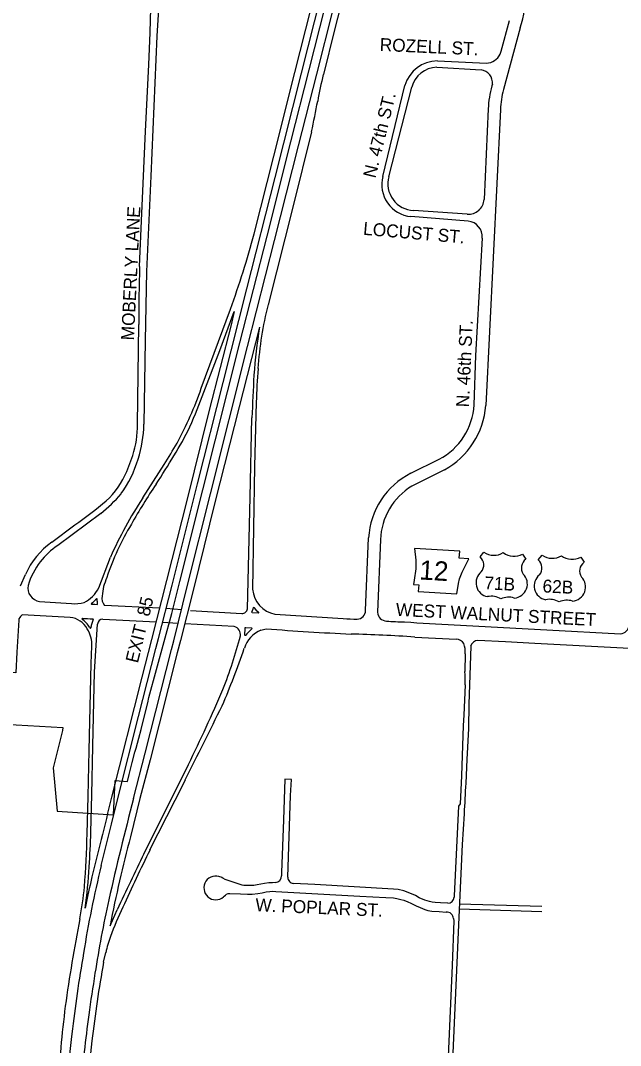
# Model space of a CAD drawing. Extents: x 0 to 712119, y 0 to 761125.
# Drawn here: x 668635 to 670960, y 734082 to 738055 of the extents above; entities that cross this region are included whole.
import ezdxf

# ---------------------------------------------------------------- set-up
doc = ezdxf.new("R2010")
doc.units = 0
for name, color, linetype in [('city boundary', 7, 'Continuous'), ('Exit #s', 7, 'Continuous'), ('HWY signs', 7, 'Continuous'), ('PAVED ROADS', 7, 'Continuous'), ('street names', 7, 'Continuous')]:
    doc.layers.add(name, color=color, linetype=linetype)

msp = doc.modelspace()

# ---------------------------------------------------------------- linework, layer by layer
at = {"layer": 'city boundary'}
msp.add_lwpolyline([(668436.5, 735335.1), (668799.7, 735315.2), (668798.5, 735303.7), (668762.3, 735158.2), (668776.8, 734990.1), (668995.9, 734976.3), (669002.2, 735108.9), (669049.3, 735105.9), (669056, 735132.9), (669067.6, 735179.7), (669077.6, 735219.5), (669083.7, 735234.7), (669093.4, 735273.9), (669102.4, 735306.9), (669116.4, 735365.2), (669128.1, 735411.1), (669133, 735431.7), (669221, 735756.7), (669252.5, 735881.3), (669341.5, 736235.9), (669485.3, 736806.3), (669591, 737219.4), (669683, 737585.7), (669753.1, 737863.7), (669877.4, 738354.3)], dxfattribs=at)
at = {"layer": 'HWY signs'}
msp.add_lwpolyline([(670325.4, 735832.6), (670331.9, 735873), (670336.6, 735890.7), (670346.8, 735917.4), (670357.6, 735939.8), (670372.3, 735968.9), (670335.4, 735971.1), (670337, 735998.5), (670161.6, 736009.1), (670167, 735963.5), (670166.5, 735930.4), (670160.9, 735886.1), (670158, 735868.6), (670178.2, 735867.4), (670176.6, 735841.6)], close=True, dxfattribs=at)
for points in [[(670415.9, 735976.2), (670430.9, 735994.7)], [(670505.9, 735992.7), (670505.9, 735992.7)], [(670580.6, 735986.9), (670593.6, 735967)], [(670641.4, 735964.5), (670656.5, 735982.9)], [(670731.4, 735980.9), (670731.4, 735980.9)], [(670806.1, 735975.1), (670819.2, 735955.2)]]:
    msp.add_lwpolyline(points, dxfattribs=at)
for centre, radius, start, end in [((670388.7, 735944.9), 41.5, 320.1078, 49.1208), ((670469.9, 736050.8), 68.4, 235.2382, 301.7199), ((670547.7, 736046.8), 68.4, 232.3011, 298.7827), ((670617.4, 735933), 41.5, 124.9002, 213.9131), ((670614.2, 735933.1), 41.5, 320.1078, 49.1208), ((670695.4, 736039.1), 68.4, 235.2382, 301.7199), ((670773.2, 736035), 68.4, 232.3011, 298.7827), ((670454.6, 735875.8), 54.5, 128.6765, 259.9158), ((670842.9, 735921.2), 41.5, 124.9002, 213.9131), ((670544.7, 735871.1), 54.5, 274.1051, 45.3444), ((670680.1, 735864), 54.5, 128.6765, 259.9158), ((670770.2, 735859.3), 54.5, 274.1051, 45.3444), ((670459.4, 735750), 73.6, 59.7374, 101.2498), ((670526.8, 735746.4), 73.6, 72.7711, 114.2835), ((670684.9, 735738.2), 73.6, 59.7374, 101.2498), ((670752.3, 735734.7), 73.6, 72.7711, 114.2835)]:
    msp.add_arc(centre, radius, start, end, dxfattribs=at)
at = {"layer": 'PAVED ROADS'}
for points in [[(668947.9, 734779.4), (668988.3, 734940.4), (669013, 735044.3), (669091.8, 735357.5), (669159.4, 735621.1), (669170.4, 735660.5), (669222.6, 735866.3), (669320.6, 736259.4), (669420.1, 736652.6), (669512.8, 737015.7), (669621.8, 737446.7), (669724.1, 737851.2), (669851.1, 738352.5)], [(669073.1, 735040.2), (669117.9, 735215.3), (669220.1, 735617.2), (669228.7, 735650.4), (669282.8, 735866.3), (669371.2, 736220.6), (669515.1, 736792.2), (669619.8, 737203.2), (669712.7, 737570.2), (669783.1, 737847.8), (669910.5, 738349.5)], [(669096.8, 737101.7), (669104.2, 737279.4), (669120.1, 737626.9), (669132, 737883.6), (669137.1, 738009.3), (669147.2, 738340.5)], [(669540.8, 737228.7), (669616.5, 737529.2), (669698.4, 737853.5), (669825, 738353.5)], [(669935.5, 738347.4), (669852.2, 738018.6), (669808.6, 737846.6)], [(669180.8, 738339.2), (669173.7, 738163.6), (669163.5, 737994.6), (669140.2, 737451.6), (669123.6, 737082.4), (669118.6, 736815.3), (669113.3, 736490.2)], [(670493.5, 737925.5), (670497.5, 737936), (670530, 738055.5)], [(670571.5, 738027), (670506.5, 737787.5)], [(670248, 737874), (670420, 737864.5)], [(670250.5, 737898.5), (670440.5, 737890)], [(670039, 737451), (670125, 737804)], [(670062.5, 737450), (670151.2, 737796.5)], [(670464, 737808), (670462, 737802)], [(670447.4, 737713.1), (670431.5, 737361.5)], [(670494.5, 737710.5), (670437.9, 736563.2)], [(670447.4, 737713.1), (670447.4, 737713.1)], [(669763, 737624), (669691.4, 737336.9), (669594.7, 736953.9)], [(670366.4, 737304.5), (670158.5, 737319.5)], [(670369.5, 737278), (670147.5, 737295.5)], [(670392.6, 736565.6), (670399.6, 736756.6), (670424.7, 737211.7)], [(669345.4, 736614.6), (669407, 736776.4), (669463.4, 736927.7), (669450.9, 736876.1), (669366.6, 736545.1), (669279.5, 736195.1), (669143.4, 735656.2), (669105.8, 735510.6), (668988.1, 735044.4)], [(669335.6, 736630.1), (669402.4, 736810.7), (669448.9, 736936.2)], [(669088.8, 736489.8), (669093.1, 736877)], [(669561.1, 736866.5), (669482.1, 736558.5), (669388, 736186.9), (669305, 735851.3), (669254.7, 735651.5), (669242.4, 735604.6), (669137, 735189.4), (669098.2, 735040), (669061.2, 734891.4)], [(669548.6, 736575.8), (669541.4, 736326.2), (669534.7, 735850.7)], [(669514.6, 735775.3), (669525.2, 736207.1), (669532, 736514.7)], [(669047.1, 736307.5), (669070.7, 736369.6)], [(670148, 736300.3), (670257.3, 736354.5)], [(669109, 736204.7), (669192.1, 736334.7)], [(670278, 736313.4), (670151.3, 736250.7)], [(668946, 736144.7), (668779.3, 736020.5)], [(668756.3, 736032.8), (668845.5, 736099.9)], [(669972.2, 735768.4), (669983.8, 736050.1)], [(670029.6, 736043), (670019.1, 735761.4)], [(668938.4, 735855.9), (668983.5, 735975.2)], [(668635.2, 735863.5), (668654.2, 735907.7)], [(668708.7, 735803.1), (668832.8, 735795.6)], [(668827.3, 735741.4), (668642.1, 735751.1), (668635.4, 735745.3), (668632.2, 735741), (668629.2, 735735.5), (668628.7, 735730.6), (668620.8, 735606.4), (668617.6, 735527.4), (668590.6, 735527.9), (668595.6, 735628.9), (668599.1, 735724.9), (668599, 735728.8), (668598.9, 735732.7), (668598.6, 735736.4), (668597.5, 735742.1), (668595.8, 735746.6), (668593.2, 735751), (668588.7, 735752.7), (668579.2, 735754.4), (668532.3, 735757.2), (668296.5, 735776.9)], [(669173.7, 735777.5), (668960.8, 735788.3)], [(669258.4, 735771.4), (669199.9, 735775.6)], [(669294.4, 735768), (669492.3, 735757.1)], [(668873.6, 735734.5), (668873.6, 735734.5)], [(669245.2, 735717.9), (669186.4, 735721.5)], [(669620.7, 735753.8), (669885.5, 735737.1)], [(668903.2, 735703.3), (668905.3, 735700.3)], [(668907.8, 734909.1), (668911.3, 735053.3), (668915.1, 735242.6), (668922.2, 735530.4), (668933.3, 735715.8)], [(669463.1, 735705.8), (669271.6, 735716.8)], [(669566.6, 735692.5), (669587.2, 735697.5)], [(670315.7, 735712.3), (670674.2, 735694.1), (670960, 735678)], [(670163.6, 735665.6), (670242.8, 735660.8), (670323.9, 735657.2)], [(671664, 735592), (671344.7, 735603.9), (670995.3, 735620.5), (670627.9, 735640.5), (670515, 735647.1), (670407.6, 735652.5)], [(668893.7, 734902.3), (668897.6, 735048), (668901, 735226), (668908.9, 735563.3), (668912, 735629.7)], [(670358.1, 735600.7), (670357.1, 735531.6)], [(670379.5, 735629.9), (670372.7, 735404.8), (670371.4, 735311.1), (670364.2, 735191.4), (670360.5, 735098.8)], [(670357.8, 735479.8), (670352.7, 735362.7), (670350.7, 735322.6), (670344.1, 735127.5), (670338.2, 735019.4), (670331.9, 735009.9), (670316, 734663), (670316, 734657.5)], [(669112.9, 734825.2), (669215.8, 735030.9), (669285.8, 735172)], [(669136.9, 734841), (669234.5, 735033.8), (669273.9, 735112.2)], [(669671.4, 734734.3), (669682, 735051), (669685, 735113.5), (669659, 735114.5), (669654.5, 734957.5), (669647, 734753), (669646.9, 734740.5)], [(670354.2, 734980.4), (670346.7, 734861.8), (670333, 734579.2), (670322.8, 734344.7), (670306.5, 733965.5), (670286.7, 733516.2), (670268, 733065.2)], [(669623.2, 734713.5), (669612, 734713.3), (669597.5, 734712.7), (669580.8, 734710.8), (669566.1, 734708.2), (669551.6, 734704.6), (669539.3, 734702.6), (669525.3, 734702), (669513, 734701.9), (669500.1, 734703), (669493.8, 734704.3), (669428.4, 734726.1), (669418.6, 734731), (669412.1, 734734.6)], [(670290.5, 734634), (670262, 734635.5), (670242.5, 734636.5), (670230, 734637.5), (670220.5, 734640), (670202.5, 734646), (670180.5, 734655), (670165.5, 734663.5), (670144, 734673), (670120, 734681.5), (670098, 734686.5), (670081, 734688.5), (669776, 734706), (669692.9, 734710.4)], [(669421.9, 734658), (669425, 734661.5), (669429, 734665.5), (669434, 734669), (669439.5, 734671), (669446, 734671.5), (669487.5, 734669.5), (669514.5, 734668.5), (669533, 734669), (669554.5, 734671), (669572, 734674), (669586.5, 734677.5), (669601, 734679.5), (669611.5, 734680), (669625, 734679.5), (669950, 734661.5), (670050.5, 734656), (670080.5, 734654.5), (670094, 734652), (670109.5, 734648.5), (670121, 734645), (670136, 734639), (670148, 734634), (670168.5, 734623), (670184, 734617), (670202.5, 734610), (670213.5, 734606), (670228.5, 734603), (670258, 734601), (670285, 734599.5)], [(668982.1, 734545.8), (669010.1, 734608.7)], [(670334.9, 734611.9), (670654.9, 734602.2)], [(670335.5, 734631.9), (670655.5, 734622.2)], [(670312.5, 734574), (670314.5, 734565.5), (670308.4, 734391.9), (670292.4, 734039.4), (670278, 733725.7), (670264.5, 733399.3), (670250.1, 733065.8), (670248.3, 733062.6)], [(668957.4, 734405.5), (668965.4, 734442.1)]]:
    msp.add_lwpolyline(points, dxfattribs=at)
for points in [[(668930.9, 735813.6), (668926.3, 735809.5), (668919.4, 735803.4), (668913.6, 735798.5), (668908.5, 735794.5), (668909.8, 735793.5), (668923.7, 735792.5), (668933.4, 735792.3), (668933.4, 735792.3), (668934, 735793.6), (668933.7, 735797.6), (668933.5, 735800), (668933.1, 735802.5), (668932.9, 735805.3), (668932.6, 735808.6), (668932.3, 735813.1)], [(669539.4, 735780.5), (669547.4, 735771.6), (669557.3, 735761.3), (669557.1, 735759.8), (669556.2, 735758.4), (669533, 735759.2), (669532.3, 735760), (669532.2, 735762), (669534.6, 735768.4), (669537, 735775.3), (669538.2, 735780.1), (669538.7, 735780.9)], [(669504.8, 735673.3), (669505.4, 735699.6), (669506.2, 735702.2), (669508.2, 735703), (669530.3, 735701.2), (669532.3, 735698.9), (669532.2, 735697.4), (669530.7, 735695.4), (669521.9, 735688.1), (669512.4, 735678.4), (669508.9, 735673), (669507.2, 735671.9), (669505.5, 735671.9)]]:
    msp.add_lwpolyline(points, close=True, dxfattribs=at)
for centre, radius, start, end in [((670084.2, 738178.8), 510.4, 342.698, 358.9012), ((670438.2, 737950.7), 60.8, 272.1694, 335.4599), ((670250.8, 737767.5), 131, 90.1262, 163.8098), ((670251, 737771.1), 103, 91.689, 165.697), ((670412.3, 737813.2), 51.9, 354.3071, 81.5131), ((671021.8, 737537.4), 1252, 165.703, 170.5584), ((670815.7, 737698.1), 368.6, 163.6357, 177.6794), ((670879.1, 737690), 385.1, 165.335, 176.9491), ((663007.5, 739037.1), 6901.7, 348.18506, 349.19126), ((670159.3, 737419.3), 124.4, 165.2389, 264.5719), ((670161.3, 737422.1), 102.7, 164.2416, 268.4372), ((670370.6, 737365.3), 61, 266.0958, 356.4632), ((670362.6, 737216.2), 62.2, 355.8511, 83.6694), ((665647.2, 738290.9), 4035.9, 340.3867, 344.7406), ((674900.1, 736892.5), 5807, 177.93564, 180.15304), ((670852.5, 736627.5), 1299.5, 165.4514, 176.5087), ((671742.8, 736522.7), 2208.7, 171.0448, 175.8898), ((675213.5, 736332.2), 5684.4, 176.4815, 178.1599), ((672266.8, 736498.7), 2719.3, 175.6151, 178.3752), ((668042.4, 737073.6), 1367.1, 331.3178, 341.0722), ((667346.1, 737342.2), 2127.7, 336.1138, 340.0011), ((670137.5, 736580.1), 255.5, 297.9703, 356.7427), ((670125.5, 736587), 313.3, 299.1346, 355.6296), ((668663.8, 736492.3), 425, 343.2173, 359.6623), ((668661.9, 736495.3), 451.4, 341.8991, 359.3533), ((668212.9, 736999.1), 1196.8, 328.1916, 334.329), ((662655.2, 740312.2), 7652, 328.68101, 329.40326), ((668660.6, 736483.8), 449.2, 324.2463, 343.3563), ((665309.9, 738754.3), 4589, 327.0517, 328.6731), ((668743.5, 736435.2), 329.4, 312.796, 337.1835), ((670281.2, 736033.9), 297.8, 116.561, 176.8854), ((671156.3, 734918), 2403.9, 146.1115, 150.4642), ((670286.9, 736031.9), 257.5, 121.7794, 177.5139), ((668638.8, 736540.9), 501.4, 307.7875, 320.3975), ((670506.5, 735291.3), 1669.5, 146.8323, 155.8171), ((667933.1, 737412.7), 1598.6, 304.8, 310.3067), ((669920.8, 735583.8), 1001.1, 148.7568, 161.8429), ((668931.7, 735785.5), 303.2, 125.3492, 156.2232), ((668940.2, 735781.1), 288.4, 123.9065, 142.3435), ((668944.1, 735779.4), 292.6, 142.5484, 162.8814), ((669161.8, 735809.4), 210.8, 155.805, 175.8937), ((668716.9, 735855.8), 53.3, 169.4717, 261.1329), ((668819, 735918.7), 135, 297.7825, 332.2587), ((669641.3, 735858.8), 106.9, 184.3097, 258.8783), ((668848.1, 735919.4), 124.7, 262.9679, 285.7062), ((668991.3, 735815.4), 40.8, 167.2031, 221.6813), ((669494.4, 735777.3), 20.3, 264.1556, 354.5177), ((669939.4, 735767.6), 32.8, 271.2599, 1.4134), ((670053.8, 735762.2), 34.7, 181.2907, 268.8758), ((668819.8, 735658.7), 83.1, 27.2299, 84.8377), ((668874.8, 735736), 1.88, 82.6087, 230.8204), ((668811.5, 735646.2), 108, 31.8893, 54.872), ((669061.9, 739714.1), 3980.7, 267.3095, 267.8851), ((669016.2, 735688.6), 108.8, 155.6344, 173.2113), ((668915.1, 735734.1), 2.08, 343.3046, 93.4827), ((668954.7, 735713), 21.5, 90.0053, 172.4795), ((670331.9, 760516.5), 24820.2, 266.81918, 267.29433), ((669957.6, 736779.6), 1045, 266.0415, 269.0404), ((670159.2, 737267.7), 1543.9, 266.0582, 268.6746), ((674627.9, 806287.6), 70707, 266.34746, 266.503536), ((668793.1, 735633.2), 119, 358.2855, 32.2478), ((668906.3, 735702), 2, 240.4938, 343.9125), ((669456.5, 735675.3), 31.2, 349.9175, 77.8969), ((669612.6, 735586.5), 115.6, 113.4548, 162.1726), ((670387.4, 745928), 10261.7, 265.52792, 267.36636), ((670957, 735714), 36.1, 274.7636, 355.2364), ((667806.9, 736103.2), 1735.3, 338.3305, 345.5377), ((669712.3, 728641), 7039, 86.32426, 88.34332), ((670321.8, 735620.9), 36.4, 31.6194, 86.702), ((670278.7, 735609.8), 80, 353.4585, 22.1496), ((670409.8, 735621), 31.6, 93.8976, 163.7535), ((666131.4, 736790.2), 3567.8, 337.0547, 340.8846), ((669687.1, 735496.9), 670.9, 358.5394, 2.9639), ((663859.3, 737847), 6050, 333.75955, 336.78843), ((464028.2, 837578.2), 229401.5, 333.469993, 333.550106), ((676633.8, 734705), 6285.6, 176.40866, 177.4888), ((1043033.7, 642741.9), 385266, 166.138188, 166.188458), ((680769.7, 731981.6), 12089.8, 165.34553, 167.26712), ((663589.1, 735072.5), 5307.3, 355.9469, 358.1626), ((666089.7, 734978.7), 2818.9, 355.8445, 358.5842), ((676778.4, 732885.3), 7973.7, 165.42835, 166.69081), ((678202.3, 730379.5), 10118.4, 153.93639, 155.29349), ((677728.7, 730634.6), 9566.1, 153.9144, 155.3928), ((673178.6, 733749), 4354.4, 166.313, 170.8678), ((666421.8, 734928.2), 2484.2, 352.7549, 356.4511), ((669392.1, 734693.1), 46.1, 64.3188, 310.3051), ((669620.6, 734739.7), 26.3, 275.6578, 1.6258), ((669693.7, 734732.7), 22.3, 175.9289, 267.9415), ((667369.6, 734858.2), 1522.1, 349.184, 353.9361), ((683746.1, 731573.5), 15168, 168.0422, 168.43265), ((675203, 733331.2), 6338.3, 167.3348, 168.95249), ((673828, 733588.8), 4964.8, 167.7024, 171.039), ((670290.4, 734659.7), 25.7, 270.3303, 354.9951), ((670091.9, 734106.2), 1177.6, 154.2435, 160.2092), ((675759.6, 733257.6), 7019.2, 169.20244, 172.00158), ((670287, 734574), 25.5, 359.9054, 94.4168), ((669501.5, 734319.1), 550, 160.2577, 167.0828), ((674675, 733438.1), 5881.5, 170.19024, 173.26645), ((673462.1, 733581.3), 4579.5, 169.6313, 173.4957), ((677878.2, 732933.7), 9067.6, 170.9365, 171.96773), ((673421.5, 733652.6), 4649.3, 172.8133, 176.7725), ((674659.2, 733420.3), 5812.3, 172.28319, 175.12676), ((674194.5, 733467.8), 5400.9, 172.9817, 176.8749), ((673330.3, 733543.2), 4453.2, 172.8168, 177.8598)]:
    msp.add_arc(centre, radius, start, end, dxfattribs=at)

# ---------------------------------------------------------------- texts
at = {"layer": 'Exit #s'}
msp.add_text('EXIT  85', height=50, rotation=76.35, dxfattribs=at).set_placement((669089.9, 735561.9))
at = {"layer": 'HWY signs'}
for s, height, rotation, p in [('12', 75, 356.5521, (670179.5, 735889)), ('71B', 50, 357.0105, (670431.5, 735850.8)), ('62B', 50, 357.0105, (670657, 735839))]:
    msp.add_text(s, height=height, rotation=rotation, dxfattribs=at).set_placement(p)
at = {"layer": 'street names'}
for s, rotation, p in [('ROZELL ST.', 357.4097, (670026.3, 737937.7)), ('N. 47th ST.', 76.3176, (670010.3, 737441.7)), ('MOBERLY LANE', 87.1965, (669074.6, 736814.6)), ('LOCUST ST.', 355.0441, (669961.4, 737224.8)), ('N. 46th ST.', 87.4526, (670372.8, 736555.4)), ('WEST WALNUT STREET', 357.049, (670088.6, 735747.9)), ('W. POPLAR ST.', 357.4154, (669544.4, 734603.3))]:
    msp.add_text(s, height=50, rotation=rotation, dxfattribs=at).set_placement(p)

doc.saveas('drawing.dxf')
